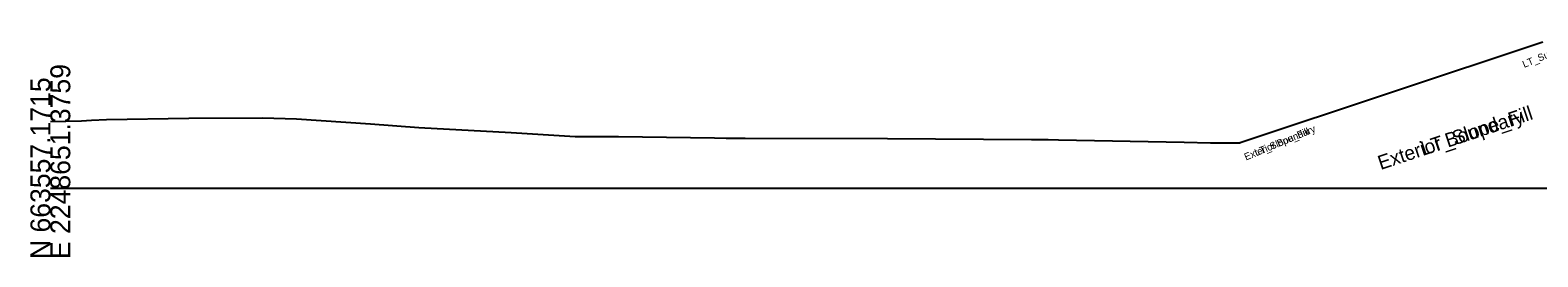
# Model space of a CAD drawing. Extents: x -26 to 2603, y -10 to 9566.
# Drawn here: x 997.2 to 1209.2, y 1990.3 to 2022.3 of the extents above; entities that cross this region are included whole.
import ezdxf

# ---------------------------------------------------------------- set-up
doc = ezdxf.new("R2010")
doc.units = 0
for name, color, linetype in [('Default', 7, 'Continuous'), ('Exist Cross Section Cell', 7, 'Continuous'), ('Exist XS Ground Line', 7, 'Continuous'), ('Scratch_Level_9', 7, 'Continuous')]:
    doc.layers.add(name, color=color, linetype=linetype)

msp = doc.modelspace()

# ---------------------------------------------------------------- linework, layer by layer
at = {"layer": 'Exist Cross Section Cell'}
msp.add_line((1000, 2000), (1300, 2000), dxfattribs=at)
at = {"layer": 'Exist XS Ground Line'}
for p, q in [((1019.48, 2009.86), (1029.84, 2009.89)), ((1029.84, 2009.89), (1034.59, 2009.76)), ((1000, 2009.37), (1004.38, 2009.5)), ((1004.38, 2009.5), (1005.8, 2009.56)), ((1005.8, 2009.56), (1007.88, 2009.68)), ((1007.88, 2009.68), (1019.48, 2009.86)), ((1034.59, 2009.76), (1045.03, 2009.04)), ((1045.03, 2009.04), (1051.81, 2008.55)), ((1051.81, 2008.55), (1064.8, 2007.84)), ((1064.8, 2007.84), (1073.78, 2007.29)), ((1073.78, 2007.29), (1079.9, 2007.25)), ((1079.9, 2007.25), (1093.39, 2007.07)), ((1093.39, 2007.07), (1095.01, 2007.05)), ((1095.01, 2007.05), (1095.74, 2007.04)), ((1095.74, 2007.04), (1097.7, 2007.04)), ((1097.7, 2007.04), (1117.71, 2007)), ((1117.71, 2007), (1137.95, 2006.86)), ((1137.95, 2006.86), (1139.68, 2006.84)), ((1139.68, 2006.84), (1140.32, 2006.84)), ((1140.32, 2006.84), (1141.75, 2006.82)), ((1141.75, 2006.82), (1159.44, 2006.47)), ((1159.44, 2006.47), (1163.15, 2006.38)), ((1163.15, 2006.38), (1167.3, 2006.38))]:
    msp.add_line(p, q, dxfattribs=at)
msp.add_lwpolyline([(1209.88, 2020.57), (1167.3, 2006.38)], dxfattribs=at)

# ---------------------------------------------------------------- texts
at = {"layer": 'Default'}
msp.add_text('-', height=0.0001, dxfattribs=at).set_placement((1000, 2000))
msp.add_text('-', height=0.0001, dxfattribs=at).set_placement((1000, 2000))
msp.add_text('-', height=0.0001, dxfattribs=at).set_placement((1000, 2000))
msp.add_text('-', height=0.0001, dxfattribs=at).set_placement((1000, 2000))
msp.add_text('-', height=0.0001, dxfattribs=at).set_placement((1000, 2000))
at = {"layer": 'Exist Cross Section Cell'}
for s, p in [('E 2248651.3759', (1002.8, 1990)), ('N 663557.1715', (1000, 1990))]:
    msp.add_text(s, height=2.8, rotation=90, dxfattribs=at).set_placement(p)
at = {"layer": 'Scratch_Level_9'}
for s, height, rotation, p in [('LT_Sub_OSS_DLT', 1, 22.5575, (1207.25, 2016.93)), ('Exterior Boundary', 2, 18.4332, (1187.07, 2002.55)), ('Exterior Boundary', 2, 18.4332, (1187.07, 2002.55)), ('LT_Slope_Fill', 2, 18.4332, (1193.12, 2004.57)), ('LT_Slope_Fill', 2, 18.4332, (1193.12, 2004.57)), ('Exterior Boundary', 1, 22.5575, (1168.13, 2003.88)), ('LT_Slope_Fill', 1, 22.5575, (1169.58, 2004.49))]:
    msp.add_text(s, height=height, rotation=rotation, dxfattribs=at).set_placement(p)

doc.saveas('drawing.dxf')
